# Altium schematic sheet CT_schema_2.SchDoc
size 454 x 403 mm
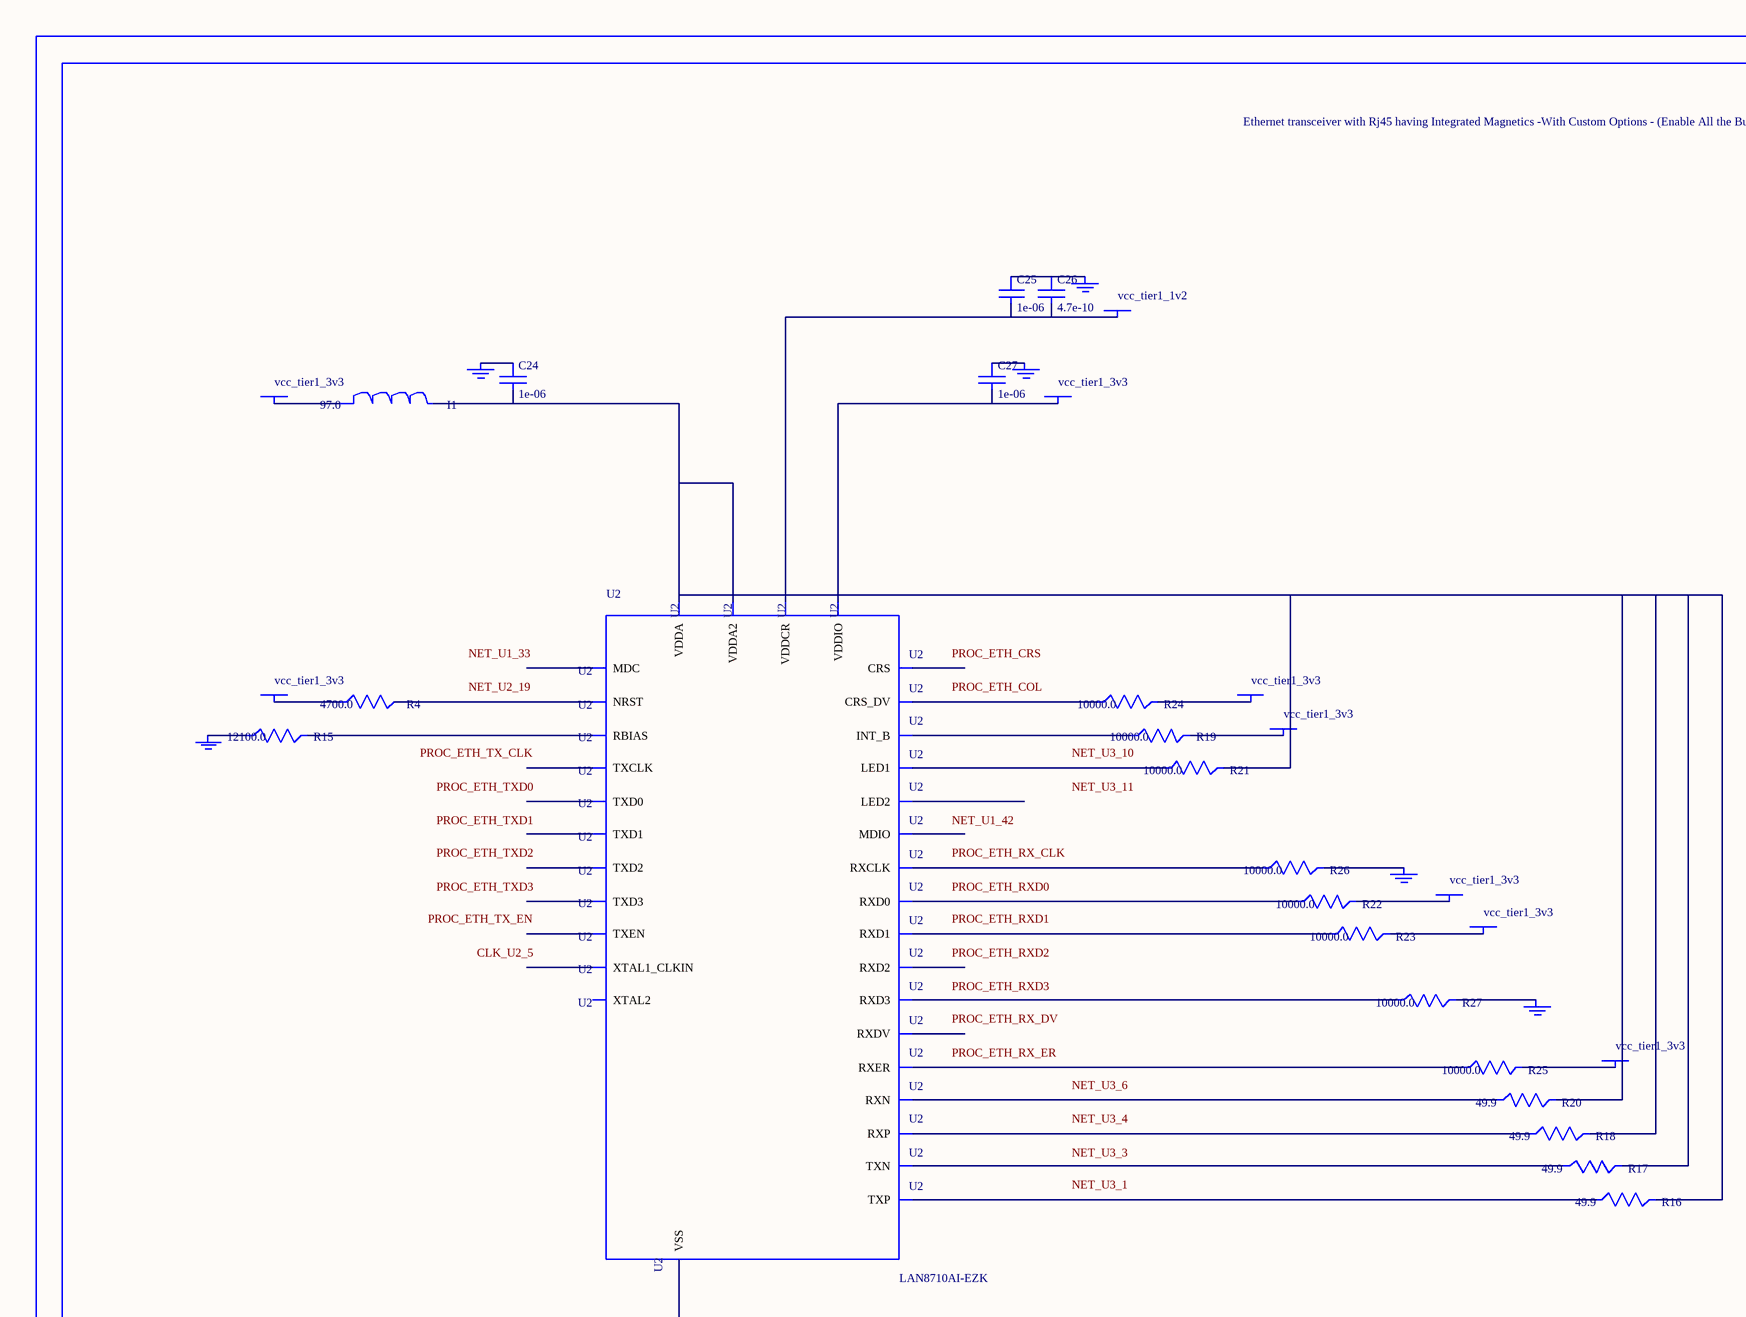
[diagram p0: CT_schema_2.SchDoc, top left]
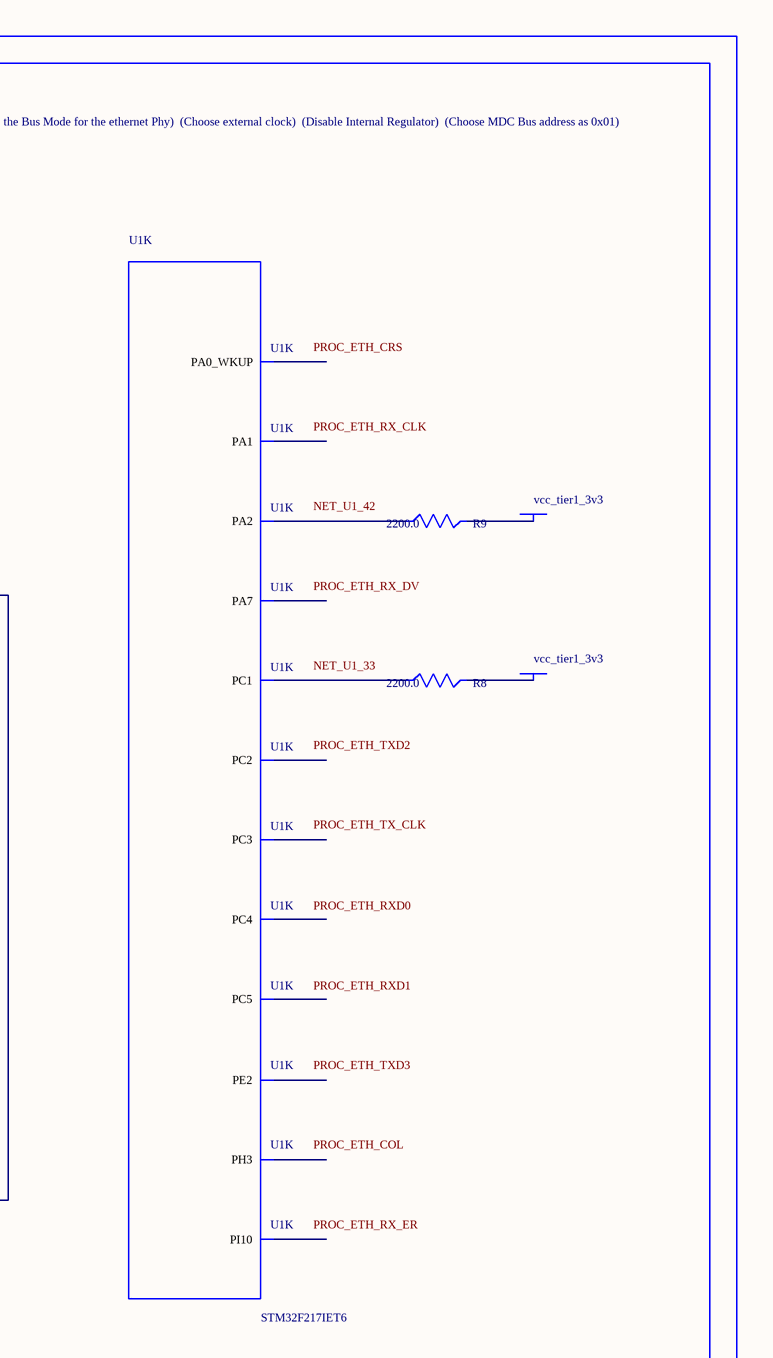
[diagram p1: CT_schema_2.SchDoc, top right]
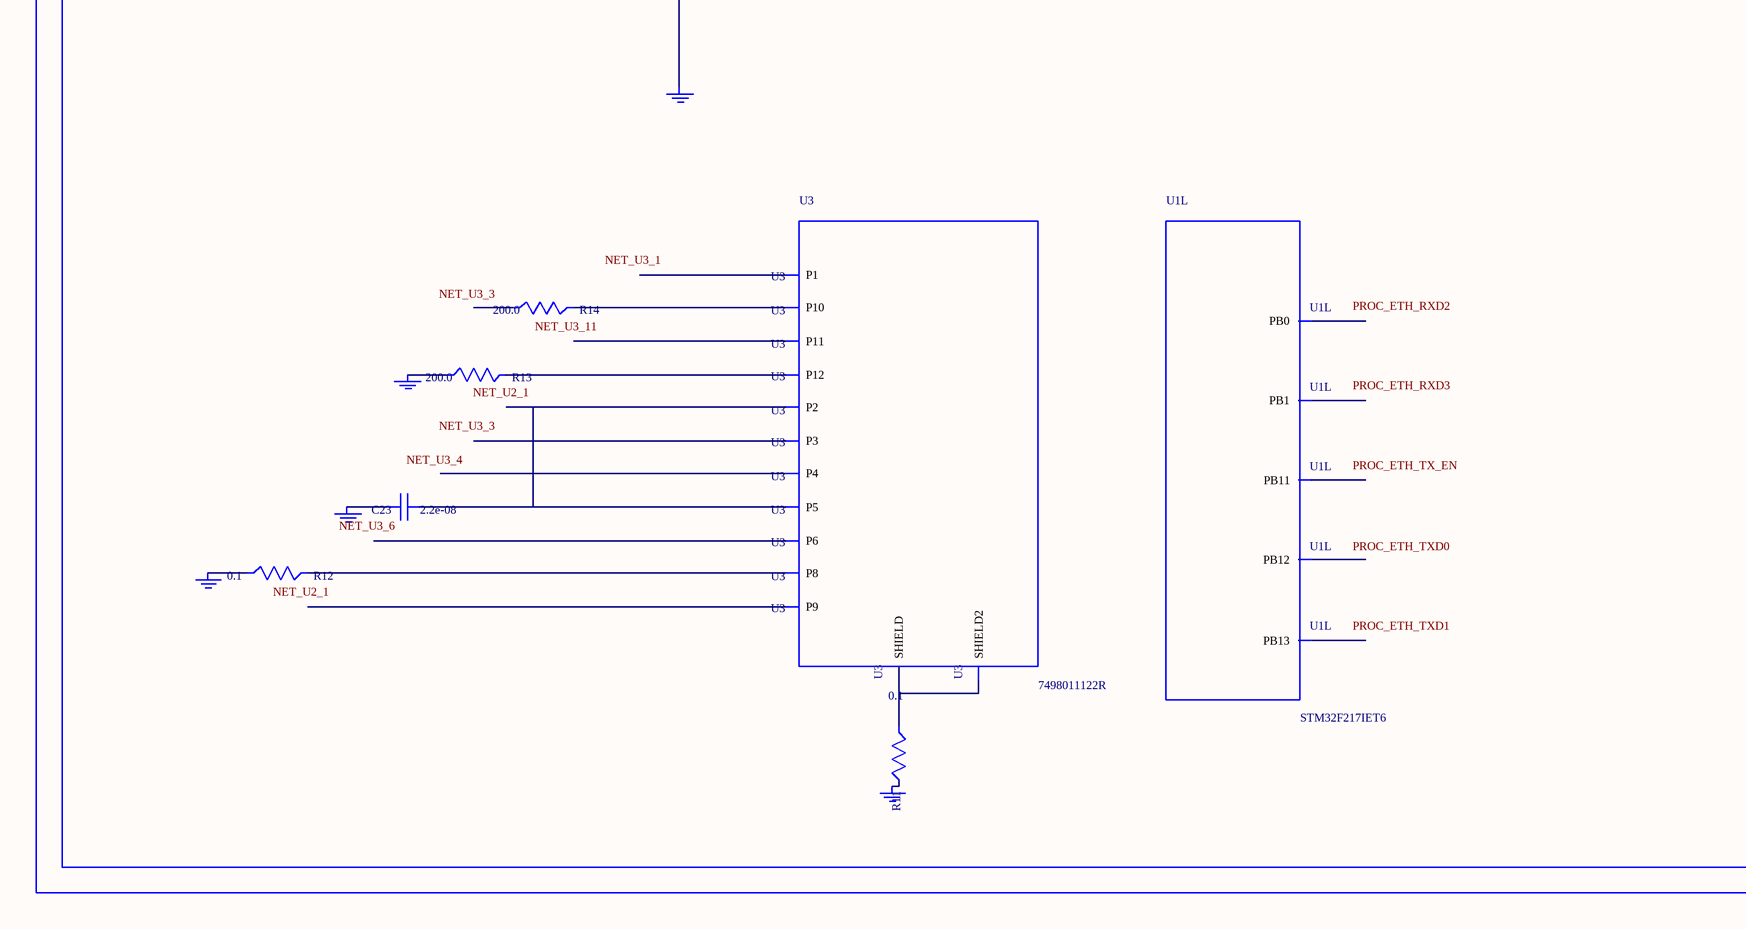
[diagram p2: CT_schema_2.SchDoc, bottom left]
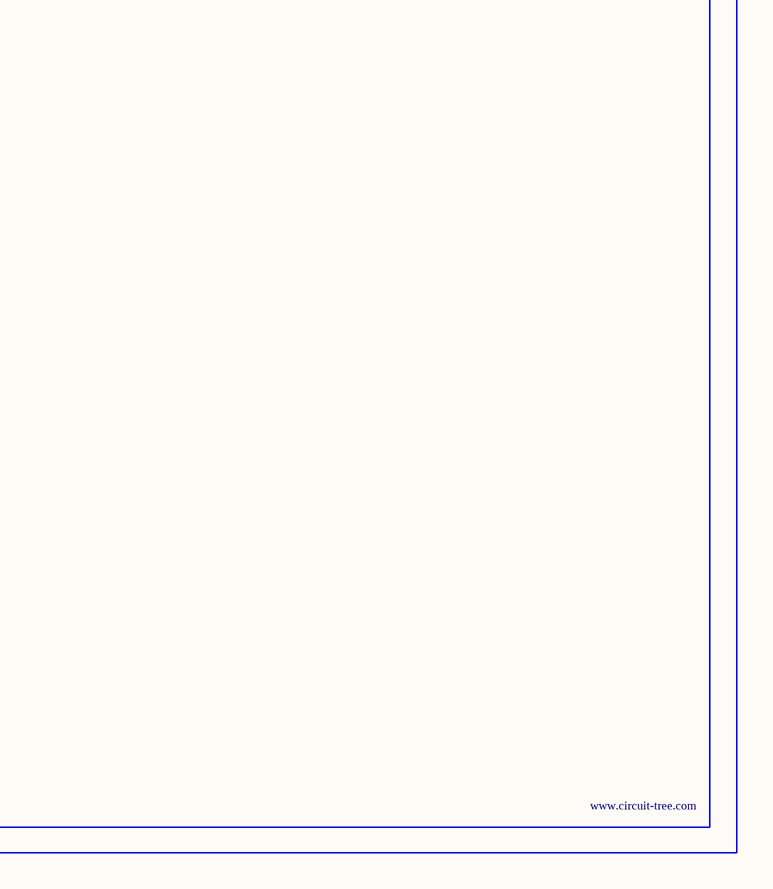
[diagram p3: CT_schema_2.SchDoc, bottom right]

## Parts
BORDER1  (no value)
C23  2.2e-08  [C0402]
C24  1e-06  [C0603]
C25  1e-06  [C0603]
C26  4.7e-10  [C0603]
C27  1e-06  [C0603]
GND_INSTANCE_1_0  (no value)
GND_INSTANCE_1_1  (no value)
GND_INSTANCE_1_2  (no value)
GND_INSTANCE_1_3  (no value)
GND_INSTANCE_1_4  (no value)
GND_INSTANCE_1_5  (no value)
GND_INSTANCE_1_6  (no value)
GND_INSTANCE_1_7  (no value)
GND_INSTANCE_1_8  (no value)
GND_INSTANCE_1_9  (no value)
GND_INSTANCE_1_10  (no value)
I1  97.0  [R0603]
POWER_INSTANCE_1_0  vcc_tier1_3v3
POWER_INSTANCE_1_1  vcc_tier1_1v2
POWER_INSTANCE_1_2  vcc_tier1_3v3
POWER_INSTANCE_1_3  vcc_tier1_3v3
POWER_INSTANCE_1_4  vcc_tier1_3v3
POWER_INSTANCE_1_5  vcc_tier1_3v3
POWER_INSTANCE_1_6  vcc_tier1_3v3
POWER_INSTANCE_1_7  vcc_tier1_3v3
POWER_INSTANCE_1_8  vcc_tier1_3v3
POWER_INSTANCE_1_9  vcc_tier1_3v3
POWER_INSTANCE_1_10  vcc_tier1_3v3
R4  4700.0  [R0603]
R8  2200.0  [R0603]
R9  2200.0  [R0603]
R11  0.1  [R0603]
R12  0.1  [R0603]
R13  200.0  [R0603]
R14  200.0  [R0603]
R15  12100.0  [R0603]
R16  49.9  [R0603]
R17  49.9  [R0603]
R18  49.9  [R0603]
R19  10000.0  [R0603]
R20  49.9  [R0603]
R21  10000.0  [R0603]
R22  10000.0  [R0603]
R23  10000.0  [R0603]
R24  10000.0  [R0603]
R25  10000.0  [R0603]
R26  10000.0  [R0603]
R27  10000.0  [R0603]
U1  STM32F217IET6  [LQFP176]  (parts K,L of 14)
U2  LAN8710AI-EZK  [QFN-32]
U3  7498011122R  [7498011122R]

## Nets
NetC23_1: C23.1 U3.2(P2) U3.5(P5)
NetC23_2: C23.2 GND_INSTANCE_1_7.0(GND)
NetC24_1: C24.1 GND_INSTANCE_1_0.0(GND)
NetC24_2: C24.2 I1.2 R16.2 R17.2 R18.2 R20.2 R21.2 U2.1(VDDA) U2.27(VDDA2)
NetC25_1: C25.1 C26.1 GND_INSTANCE_1_1.0(GND)
NetC25_2: C25.2 C26.2 POWER_INSTANCE_1_1.0(PWR) U2.6(VDDCR)
NetC27_1: C27.1 GND_INSTANCE_1_4.0(GND)
NetC27_2: C27.2 POWER_INSTANCE_1_4.0(PWR) U2.12(VDDIO)
NetGND_INSTANCE_1_2_0: GND_INSTANCE_1_2.0(GND) R26.2
NetGND_INSTANCE_1_3_0: GND_INSTANCE_1_3.0(GND) R27.2
NetGND_INSTANCE_1_5_0: GND_INSTANCE_1_5.0(GND) R15.1
NetGND_INSTANCE_1_6_0: GND_INSTANCE_1_6.0(GND) U2.EXP(VSS)
NetGND_INSTANCE_1_8_0: GND_INSTANCE_1_8.0(GND) R12.1
NetGND_INSTANCE_1_9_0: GND_INSTANCE_1_9.0(GND) R13.1
NetGND_INSTANCE_1_10_0: GND_INSTANCE_1_10.0(GND) R11.2
NetI1_1: I1.1 POWER_INSTANCE_1_0.0(PWR)
NetPOWER_INSTANCE_1_2_0: POWER_INSTANCE_1_2.0(PWR) R23.2
NetPOWER_INSTANCE_1_3_0: POWER_INSTANCE_1_3.0(PWR) R22.2
NetPOWER_INSTANCE_1_5_0: POWER_INSTANCE_1_5.0(PWR) R25.2
NetPOWER_INSTANCE_1_6_0: POWER_INSTANCE_1_6.0(PWR) R24.2
NetPOWER_INSTANCE_1_7_0: POWER_INSTANCE_1_7.0(PWR) R19.2
NetPOWER_INSTANCE_1_8_0: POWER_INSTANCE_1_8.0(PWR) R4.1
NetPOWER_INSTANCE_1_9_0: POWER_INSTANCE_1_9.0(PWR) R8.2
NetPOWER_INSTANCE_1_10_0: POWER_INSTANCE_1_10.0(PWR) R9.2
NetR4_2: R4.2 U2.19(NRST)
NetR8_1: R8.1 U1.33(PC1)
NetR9_1: R9.1 U1.42(PA2)
NetR11_1: R11.1 U3.13(SHIELD) U3.14(SHIELD2)
NetR12_2: R12.2 U3.8(P8)
NetR13_2: R13.2 U3.12(P12)
NetR14_2: R14.2 U3.10(P10)
NetR15_2: R15.2 U2.32(RBIAS)
NetR16_1: R16.1 U2.29(TXP)
NetR17_1: R17.1 U2.28(TXN)
NetR18_1: R18.1 U2.31(RXP)
NetR19_1: R19.1 U2.18(INT_B)
NetR20_1: R20.1 U2.30(RXN)
NetR21_1: R21.1 U2.3(LED1)
NetR22_1: R22.1 U2.11(RXD0)
NetR23_1: R23.1 U2.10(RXD1)
NetR24_1: R24.1 U2.15(CRS_DV)
NetR25_1: R25.1 U2.13(RXER)
NetR26_1: R26.1 U2.7(RXCLK)
NetR27_1: R27.1 U2.8(RXD3)

Not connected (* = marked no-connect by the designer): R14 1; U1 1(PE2) 12(PI10) 34(PC2) 35(PC3) 40(PA0_WKUP) 41(PA1) 44(PH3) 53(PA7) 54(PC4) 55(PC5) 56(PB0) 57(PB1) 80(PB11) 92(PB12) 93(PB13); U2 2(LED2) 4(XTAL2) 5(XTAL1_CLKIN) 9(RXD2) 14(CRS) 16(MDIO) 17(MDC) 20(TXCLK) 21(TXEN) 22(TXD0) 23(TXD1) 24(TXD2) 25(TXD3) 26(RXDV); U3 1(P1) 3(P3) 4(P4) 6(P6) 9(P9) 11(P11)

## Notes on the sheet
- Labels drawn without touching a wire or pin: CLK_U2_5, NET_U1_33, NET_U1_42, NET_U2_1, NET_U2_19, NET_U3_1, NET_U3_3, NET_U3_4, NET_U3_6, NET_U3_10, NET_U3_11, PROC_ETH_COL, PROC_ETH_CRS, PROC_ETH_RX_CLK, PROC_ETH_RX_DV, PROC_ETH_RX_ER, PROC_ETH_RXD0, PROC_ETH_RXD1, PROC_ETH_RXD2, PROC_ETH_RXD3, PROC_ETH_TX_CLK, PROC_ETH_TX_EN, PROC_ETH_TXD0, PROC_ETH_TXD1, PROC_ETH_TXD2, PROC_ETH_TXD3

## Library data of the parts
BORDER1 = BORDER_PAGE1
C23 = C0402C223K3RAC
C24 C25 C27 = C0603C105K3RACTU
C26 = 06031C471KAZ2A
GND_INSTANCE_1_0-GND_INSTANCE_1_10 = GND
I1 = I1
POWER_INSTANCE_1_0-POWER_INSTANCE_1_10 = PWR
R4 = RC0603JR-074K7L
R8 R9 = RC0603JR-072K2L
R11 R12 = ERJ-3RSFR10V
R13 R14 = RC0603JR-07200RL
R15 = TNPW060312K1BEEA
R16-R18 R20 = RC0603FR-0749R9L
R19 R21-R27 = RC0603JR-0710KL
